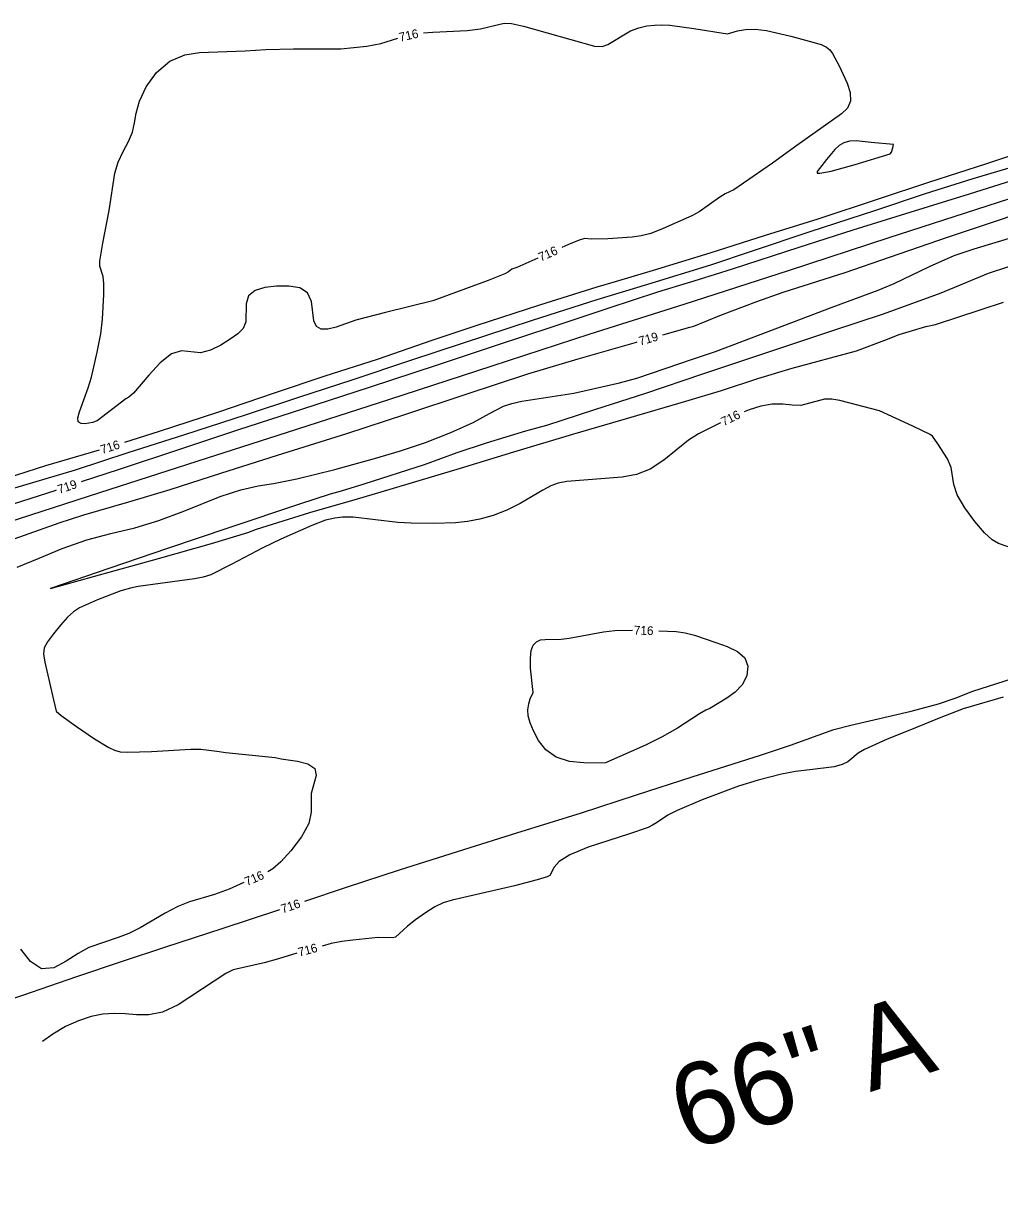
# Model space of a CAD drawing. Extents: x -468563856 to 36492962, y -306094093 to 11899197.
# Drawn here: x 1820960 to 1821405, y 530434 to 530963 of the extents above; entities that cross this region are included whole.
import ezdxf

# ---------------------------------------------------------------- set-up
doc = ezdxf.new("R2010")
doc.units = 0
for name, color, linetype in [('DT_X_Contour_Minor', 7, 'Continuous'), ('Level 14', 7, 'Continuous'), ('Level 19', 7, 'Continuous'), ('Level 40', 7, 'Continuous')]:
    doc.layers.add(name, color=color, linetype=linetype)

msp = doc.modelspace()

# ---------------------------------------------------------------- linework, layer by layer
at = {"layer": 'DT_X_Contour_Minor'}
for points in [[(1821142.3, 530958.37), (1821146.55, 530958.75), (1821162.13, 530959.43), (1821168.17, 530960.24), (1821178.97, 530962.77), (1821182.35, 530962.59), (1821187.84, 530961.37), (1821220.14, 530952.38), (1821223.59, 530952.22), (1821226.29, 530953.13), (1821236.58, 530959.23), (1821240.33, 530960.67), (1821244, 530961.53), (1821247.49, 530961.95), (1821250.83, 530962.06), (1821254.55, 530961.86), (1821265.39, 530960.41), (1821280.8, 530957.9), (1821285.27, 530959.22), (1821288.89, 530959.9), (1821293.39, 530960.09), (1821298.55, 530959.48), (1821309.65, 530956.86), (1821319.67, 530954.2), (1821323.35, 530953.03), (1821325.78, 530951.92), (1821327.35, 530950.63), (1821328.62, 530948.89), (1821331.65, 530943.38), (1821335.27, 530935.44), (1821336.6, 530931.14), (1821336.77, 530927.23), (1821335.34, 530924.06), (1821332.67, 530921.47), (1821312.28, 530907.08), (1821301.24, 530899), (1821283.64, 530886.87), (1821279.72, 530885.02), (1821277.18, 530883.53), (1821267.78, 530876.87), (1821264.43, 530875.01), (1821251.48, 530869.27), (1821245.86, 530866.96), (1821241.43, 530865.85), (1821237.39, 530865.25), (1821226.25, 530864.43), (1821218.68, 530864.35), (1821215.68, 530864.71), (1821213.61, 530864.1), (1821209.44, 530862.38), (1821205.23, 530860.51)], [(1821194.27, 530855.63), (1821184.76, 530851.4), (1821182.43, 530850.65), (1821181.04, 530849.41), (1821179.36, 530848.53), (1821171.77, 530845.5), (1821146.53, 530836.25), (1821124.97, 530830.95), (1821111.38, 530827.49), (1821102.5, 530824.2), (1821098.74, 530823.31), (1821095.69, 530823.32), (1821093.51, 530824.52), (1821092.24, 530827.18), (1821091.18, 530835.94), (1821089.47, 530839.86), (1821085.87, 530842.13), (1821080.9, 530842.98), (1821075.34, 530842.91), (1821070, 530842.31), (1821065.53, 530840.97), (1821062.6, 530838.54), (1821061.54, 530834.88), (1821061.31, 530826.69), (1821060.04, 530823.62), (1821057.61, 530821.15), (1821054.17, 530818.74), (1821049.92, 530816.09), (1821045.25, 530813.78), (1821040.61, 530812.61), (1821032.05, 530813.39), (1821027.44, 530812.12), (1821022.24, 530807.97), (1821017.11, 530802.3), (1821010.15, 530794.09), (1821007.98, 530792.36), (1821006.67, 530791.56), (1820993.66, 530781.5), (1820991.51, 530780.8), (1820988.19, 530780.22), (1820986.27, 530780.27), (1820984.98, 530781.08), (1820984.79, 530782.94), (1820985.49, 530785.66), (1820989.49, 530796.64), (1820990.95, 530801.48), (1820993.65, 530812.8), (1820995.28, 530821.18), (1820996.01, 530827.94), (1820996.67, 530839.05), (1820996.68, 530844.09), (1820996.29, 530847.3), (1820994.84, 530852.01), (1820994.88, 530854.3), (1820996.22, 530862.55), (1820999.07, 530877.36), (1821001.63, 530894.42), (1821003.16, 530899.51), (1821005.4, 530904.34), (1821007.81, 530908.87), (1821009.69, 530913.15), (1821010.64, 530917.31), (1821011.36, 530921.8), (1821012.88, 530927.19), (1821015.98, 530933.7), (1821020.65, 530940.28), (1821026.64, 530945.52), (1821033.54, 530948.4), (1821040.28, 530949.46), (1821060.95, 530950.12), (1821070.37, 530950.79), (1821083, 530951.08), (1821104.65, 530951.15), (1821116.45, 530952.3), (1821122.8, 530953.46), (1821130.55, 530955.9)], [(1821251.22, 530820.8), (1821263.56, 530824.25), (1821265.44, 530824.75), (1821277.23, 530829.55), (1821294.11, 530835.98), (1821306.1, 530840.14), (1821334.35, 530849.22), (1821354.52, 530856.11), (1821381.43, 530865.42), (1821404.23, 530873.06), (1821430.88, 530882.06), (1821456.62, 530890.46), (1821484.17, 530899.5), (1821512.94, 530908.96), (1821514.19, 530909.36)], [(1821424.26, 530907.13), (1821398.74, 530898.66), (1821372.33, 530890.14), (1821349.44, 530882.5), (1821321.84, 530873.5), (1821297.96, 530866), (1821272.68, 530857.92), (1821246.92, 530850.02), (1821229.6, 530844.93), (1821221.22, 530842.53), (1821195.12, 530834.27), (1821166.08, 530824.87), (1821146.1, 530818.1), (1821121.18, 530809.54), (1821097.36, 530801.84), (1821074.19, 530794.13), (1821048.35, 530785.28), (1821021.84, 530776.74), (1821006.04, 530771.71)], [(1821356.31, 530907.56), (1821346.21, 530908.38), (1821339.35, 530909.13), (1821336.32, 530909.03), (1821333.78, 530908.32), (1821331.61, 530907.01), (1821329.63, 530905.2), (1821325.8, 530900.65), (1821321.56, 530895.23), (1821321.59, 530894.47), (1821322.86, 530894.37), (1821327.9, 530895.38), (1821338.92, 530898.3), (1821354.91, 530903.3), (1821355.48, 530903.95), (1821356.08, 530905.98), (1821356.31, 530907.56)], [(1820951.95, 530749.83), (1820983.67, 530759.18), (1821007.69, 530767.05), (1821033.47, 530775.32), (1821061.21, 530784.29), (1821085.41, 530792.26), (1821109.81, 530800.29), (1821136.44, 530809.13), (1821160.07, 530816.96), (1821191.96, 530827.37), (1821221.42, 530836.83), (1821244.39, 530843.85), (1821273.21, 530852.62), (1821292.18, 530858.98), (1821318.35, 530867.82), (1821347.86, 530877.48), (1821370.97, 530885.11), (1821392.62, 530892), (1821423.93, 530901.3)], [(1821421.18, 530894.46), (1821390.9, 530884.92), (1821361.89, 530875.96), (1821337.91, 530868.44), (1821313.25, 530860.53), (1821282.91, 530850.64), (1821267.37, 530845.81), (1821248.82, 530840.11), (1821226.66, 530832.82), (1821201.19, 530824.41), (1821175.44, 530815.9), (1821148.44, 530806.92), (1821117.55, 530796.67), (1821087.21, 530786.93), (1821057.59, 530777.24), (1821032.07, 530768.82), (1821003.6, 530759.43), (1820986.39, 530753.69)], [(1820957.18, 530714.85), (1820967.16, 530718.95), (1820977.65, 530723.39), (1820988.83, 530727.31), (1820999.9, 530730.16), (1821010.7, 530732.78), (1821021.71, 530736.1), (1821033.12, 530740.38), (1821049.65, 530747.07), (1821059.05, 530750.1), (1821066.92, 530751.94), (1821073.89, 530752.97), (1821084.56, 530755.18), (1821101.94, 530759.41), (1821119.99, 530764.32), (1821131.83, 530767.87), (1821143.12, 530771.72), (1821154.76, 530776.28), (1821164.82, 530780.81), (1821172.37, 530784.82), (1821178.77, 530788.18), (1821182.51, 530789.5), (1821187.03, 530790.51), (1821210.77, 530794.22), (1821231.55, 530798.84), (1821239.48, 530800.95), (1821265.26, 530809.73), (1821275.24, 530813.12), (1821299.29, 530822.33), (1821328.39, 530833.38), (1821349.37, 530841.1), (1821356.68, 530844.2), (1821372.83, 530851.95), (1821384.01, 530856.92), (1821393.07, 530860.01), (1821421.74, 530868.63)], [(1821408.71, 530851.67), (1821399.56, 530848.65), (1821377.9, 530839.76), (1821351.62, 530830.12), (1821328.09, 530822.35), (1821296.31, 530811.79), (1821269.33, 530802.88), (1821243.39, 530793.99), (1821220.17, 530786.58), (1821198.34, 530779.39), (1821188.75, 530776.8), (1821170.81, 530771.38), (1821157.45, 530767.03), (1821142.59, 530761.52), (1821115.08, 530752.65), (1821104.74, 530749.56), (1821099.7, 530748.19), (1821085.71, 530743.58), (1821053.51, 530732.72), (1821025.59, 530723.36), (1820999.34, 530714.46), (1820972.38, 530705.08), (1820992, 530710.55), (1821021.48, 530718.74), (1821045.72, 530725.66), (1821062.17, 530730.64), (1821066.17, 530732.17), (1821090.47, 530739.72), (1821112.17, 530746.03), (1821127.15, 530750.35), (1821159.05, 530759.94), (1821183.43, 530767.34), (1821210.26, 530775.49), (1821235.77, 530782.84), (1821261.71, 530790.54), (1821278.03, 530795.43), (1821294.61, 530800.91), (1821310.16, 530805.56), (1821339.55, 530813.42), (1821352.4, 530818.24), (1821359.02, 530820.83), (1821371.14, 530824.52), (1821375.54, 530825.43), (1821396.23, 530832.35), (1821406.47, 530835.68)], [(1820946.64, 530724.64), (1820976.29, 530735.01), (1820987.52, 530738.75), (1821008.06, 530744.62), (1821026.84, 530750.21), (1821049.96, 530757.74), (1821075.74, 530765.95), (1821107.35, 530775.78), (1821134.27, 530784.6), (1821161.74, 530793.64), (1821189.8, 530803.01), (1821212.68, 530809.74), (1821239.24, 530817.44), (1821239.67, 530817.56)], [(1821412.62, 530722.74), (1821404.22, 530725.61), (1821401.26, 530727.38), (1821397.89, 530730.55), (1821393.49, 530735.66), (1821388.93, 530741.83), (1821385.43, 530747.79), (1821383.83, 530752.59), (1821382.62, 530760.31), (1821380.9, 530764.28), (1821376.49, 530771.09), (1821374.15, 530774.55), (1821373.07, 530775.26), (1821365.12, 530779.12), (1821350, 530786.04), (1821331.89, 530790.84), (1821328.32, 530791.44), (1821324.89, 530791.36), (1821314.09, 530788.6), (1821310.15, 530788.67), (1821305.88, 530789.09), (1821301.14, 530789.11), (1821295.89, 530788.2), (1821290.57, 530786.57), (1821288.41, 530785.69)], [(1821277.55, 530780.57), (1821267.54, 530775.64), (1821263.01, 530772.71), (1821251.79, 530763.59), (1821245.57, 530759.51), (1821239.26, 530757.05), (1821232.82, 530755.88), (1821207.54, 530753.82), (1821203.55, 530753.09), (1821200.24, 530751.92), (1821196.61, 530750), (1821186.3, 530743.87), (1821180.22, 530740.76), (1821174.05, 530738.36), (1821168, 530736.68), (1821162.24, 530735.63), (1821156.89, 530735.08), (1821146.93, 530734.79), (1821136.62, 530734.85), (1821130.54, 530735.27), (1821110.17, 530737.61), (1821105.35, 530737.64), (1821101.9, 530737.25), (1821097.62, 530736.21), (1821091.41, 530733.8), (1821077.33, 530727.66), (1821069.04, 530723.71), (1821054.59, 530716.04), (1821045.32, 530711.3), (1821041.93, 530710.23), (1821037.87, 530709.5), (1821012.32, 530706.01), (1821008.8, 530705.26), (1821004.35, 530704.01), (1820993.73, 530700.02), (1820985.59, 530696.31), (1820982.87, 530694.52), (1820980.15, 530692.03), (1820976.92, 530688.47), (1820973.64, 530684.44), (1820970.99, 530680.8), (1820969.53, 530678.05), (1820969.18, 530675.35), (1820969.75, 530671.53), (1820973.73, 530654.33), (1820974.93, 530649.23), (1820977.26, 530647.27), (1820984.13, 530642.2), (1820992.34, 530636.59), (1820998.96, 530632.6), (1821001.45, 530631.42), (1821004.03, 530630.74), (1821007.49, 530630.49), (1821018.3, 530630.89), (1821036.2, 530631.9), (1821040.88, 530631.88), (1821048.12, 530630.98), (1821052.24, 530630.4), (1821074.71, 530628.03), (1821077.47, 530627.48), (1821084.86, 530626.43), (1821089.58, 530625.23), (1821092.79, 530623.13), (1821093.3, 530619.92), (1821091.04, 530611.76), (1821091.16, 530603.24), (1821090.03, 530598.06), (1821086.63, 530591.88), (1821081.9, 530585.61), (1821077.25, 530580.48), (1821073.66, 530577.29), (1821071.42, 530575.96)], [(1820994.59, 530768.11), (1820970.12, 530761), (1820956.88, 530756.85), (1820934.19, 530749.31), (1820904.48, 530739.54), (1820882.62, 530732.37), (1820856.03, 530723.29), (1820837.77, 530717.22), (1820806.61, 530707.35), (1820778.8, 530699.04), (1820759.24, 530693.04), (1820735.87, 530685.51), (1820706.09, 530675.91), (1820682.51, 530668.65), (1820656.18, 530660.32), (1820629.75, 530651.53), (1820602.88, 530642.43), (1820572.65, 530632.09), (1820547.68, 530624.01), (1820519.59, 530615.03)], [(1820975, 530749.89), (1820974.39, 530749.69), (1820955.82, 530743.7), (1820926.89, 530734.79), (1820898.46, 530725.6), (1820872.39, 530717.07), (1820843.48, 530707.6), (1820815.52, 530698.58), (1820788.91, 530689.89), (1820759.92, 530680.44), (1820733.01, 530671.94), (1820706.96, 530663.61), (1820679.3, 530654.6), (1820651.55, 530645.41), (1820642.4, 530642.94), (1820632.42, 530641.65), (1820626.79, 530640.14), (1820605.78, 530633.36), (1820576.19, 530623.56), (1820546.48, 530613.85), (1820531, 530608.69), (1820527.63, 530607.45)], [(1821249.46, 530685.8), (1821257.38, 530685.56), (1821261.39, 530684.94), (1821265.74, 530683.79), (1821275.45, 530680.49), (1821280.62, 530678.62), (1821285.29, 530676.39), (1821288.65, 530673.49), (1821290.07, 530669.72), (1821289.62, 530665.5), (1821287.55, 530661.4), (1821284.22, 530657.88), (1821280.48, 530655.09), (1821272.73, 530650.42), (1821270.95, 530649.64), (1821268.02, 530647.98), (1821257.91, 530641.47), (1821251.05, 530637.5), (1821243.45, 530633.7), (1821225.12, 530625.65), (1821223.47, 530625.54), (1821215.23, 530625.63), (1821208.8, 530626.32), (1821202.65, 530628.18), (1821197.97, 530631.57), (1821194.68, 530635.87), (1821192.42, 530640.21), (1821190.86, 530643.92), (1821189.97, 530647.06), (1821189.75, 530649.87), (1821190.17, 530652.51), (1821190.92, 530654.8), (1821192.22, 530657.78), (1821191.07, 530668.86), (1821190.97, 530673.3), (1821191.37, 530676.79), (1821192.29, 530679.26), (1821193.69, 530680.84), (1821195.54, 530681.66), (1821197.68, 530681.94), (1821205.02, 530682.01), (1821208.61, 530682.47), (1821224.25, 530685.43), (1821229.37, 530685.96), (1821237.47, 530686.11)], [(1821088.22, 530562.57), (1821107.26, 530568.98), (1821131.38, 530576.94), (1821160.6, 530586.23), (1821184.85, 530593.8), (1821214.28, 530602.95), (1821239.35, 530611.09), (1821264.7, 530619.27), (1821295.76, 530629.14), (1821309.38, 530633.71), (1821329.13, 530640.9), (1821336.97, 530642.85), (1821364.46, 530649.26), (1821376.91, 530652.52), (1821384.4, 530655.17), (1821392.57, 530658.28), (1821417.76, 530666.41)], [(1821406.37, 530655.57), (1821388.11, 530650.23), (1821377.2, 530646), (1821363.84, 530640.59), (1821353.42, 530636.41), (1821343.15, 530631.79), (1821340.28, 530630.06), (1821335.59, 530626.1), (1821333.02, 530624.84), (1821329.32, 530623.82), (1821318.29, 530622.54), (1821311.79, 530621.74), (1821305.31, 530620.51), (1821294.73, 530617.81), (1821285.8, 530614.98), (1821269.26, 530608.87), (1821257.84, 530603.95), (1821253.49, 530601.75), (1821248.36, 530598.39), (1821246.63, 530597.19), (1821244.62, 530596.18), (1821235.61, 530593.2), (1821217.25, 530587.21), (1821208.99, 530583.81), (1821204.02, 530580.72), (1821201.73, 530578.15), (1821199.88, 530574.36), (1821198.59, 530573.77), (1821194.02, 530572.32), (1821183.7, 530569.57), (1821160.66, 530564.22), (1821155.33, 530563.01), (1821151.28, 530561.8), (1821147.45, 530560.04), (1821143.1, 530557.36), (1821138.67, 530554.18), (1821134.93, 530551.15), (1821129.5, 530546.2), (1821128.12, 530545.88), (1821121.65, 530545.99), (1821110.1, 530544.87), (1821105.09, 530544.19), (1821100.21, 530543.27), (1821096.14, 530542.18)], [(1821060.46, 530571.05), (1821053.72, 530568.14), (1821046.99, 530565.6), (1821035.67, 530562.24), (1821030.32, 530560.19), (1821024.63, 530557.18), (1821013.18, 530550.39), (1821008.01, 530547.88), (1821003.23, 530546.04), (1820989.81, 530541.47), (1820984.92, 530538.84), (1820979.5, 530535.24), (1820973.83, 530532.23), (1820968.26, 530531.8), (1820963.16, 530535.19), (1820958.82, 530540.74)], [(1820697.12, 530433.81), (1820702.92, 530435.91), (1820720.48, 530442.12), (1820743.97, 530449.49), (1820769.31, 530457.58), (1820800.41, 530467.9), (1820830.85, 530478.04), (1820855.3, 530486.23), (1820887.66, 530496.79), (1820915.92, 530505.39), (1820931.79, 530510.46), (1820959.68, 530519.8), (1820984.4, 530528.33), (1821004.64, 530535.17), (1821024.92, 530541.83), (1821050.49, 530550.19), (1821076.84, 530558.79)], [(1821084.6, 530538.88), (1821076.21, 530536.28), (1821069.72, 530534.5), (1821055.62, 530531.31), (1821052.26, 530529.68), (1821030.48, 530515.31), (1821023.34, 530512.1), (1821017.07, 530510.78), (1821011.56, 530510.8), (1821006.43, 530511.28), (1821001.37, 530511.46), (1820996.2, 530511.08), (1820990.81, 530510), (1820985.11, 530508.13), (1820979.24, 530505.44), (1820973.4, 530501.99), (1820968.64, 530498.64)]]:
    msp.add_lwpolyline(points, dxfattribs=at)
at = {"layer": 'Level 14'}
msp.add_lwpolyline([(1821454.26, 530897.29), (1821404.04, 530881.11), (1821354.18, 530865), (1821308.77, 530850.11), (1821260.81, 530834.64), (1821218.05, 530821.11), (1821173.36, 530806.4), (1821126.28, 530791.17), (1821080.2, 530776.27), (1821039.06, 530763.07), (1820994.69, 530748.7), (1820952.46, 530734.98), (1820905.4, 530719.87), (1820859.85, 530704.9), (1820812.8, 530689.68), (1820765.71, 530674.39), (1820717.41, 530658.86), (1820668.82, 530642.99), (1820623, 530628.33), (1820574.95, 530612.67), (1820524.52, 530596.36)], dxfattribs=at)

# ---------------------------------------------------------------- texts
at = {"layer": 'Level 19'}
for s, rotation, p in [('716', 12.7025, (1821131.57, 530954.33)), ('716', 24.0012, (1821195.67, 530854.07)), ('719', 15.6532, (1821240.92, 530815.83)), ('716', 26.2415, (1821279.02, 530779.06)), ('716', 17.6643, (1820995.82, 530766.36)), ('719', 18.4492, (1820976.34, 530748.23)), ('716', 358.2877, (1821238.05, 530684.14)), ('716', 23.3824, (1821061.85, 530569.47)), ('716', 18.6097, (1821078.1, 530557.05)), ('716', 15.0401, (1821085.7, 530537.3))]:
    msp.add_text(s, height=4, rotation=rotation, dxfattribs=at).set_placement(p)
at = {"layer": 'Level 40'}
msp.add_text('66" A', height=37.5, rotation=17.9864, dxfattribs=at).set_placement((1821262.45, 530448.52))

doc.saveas('drawing.dxf')
